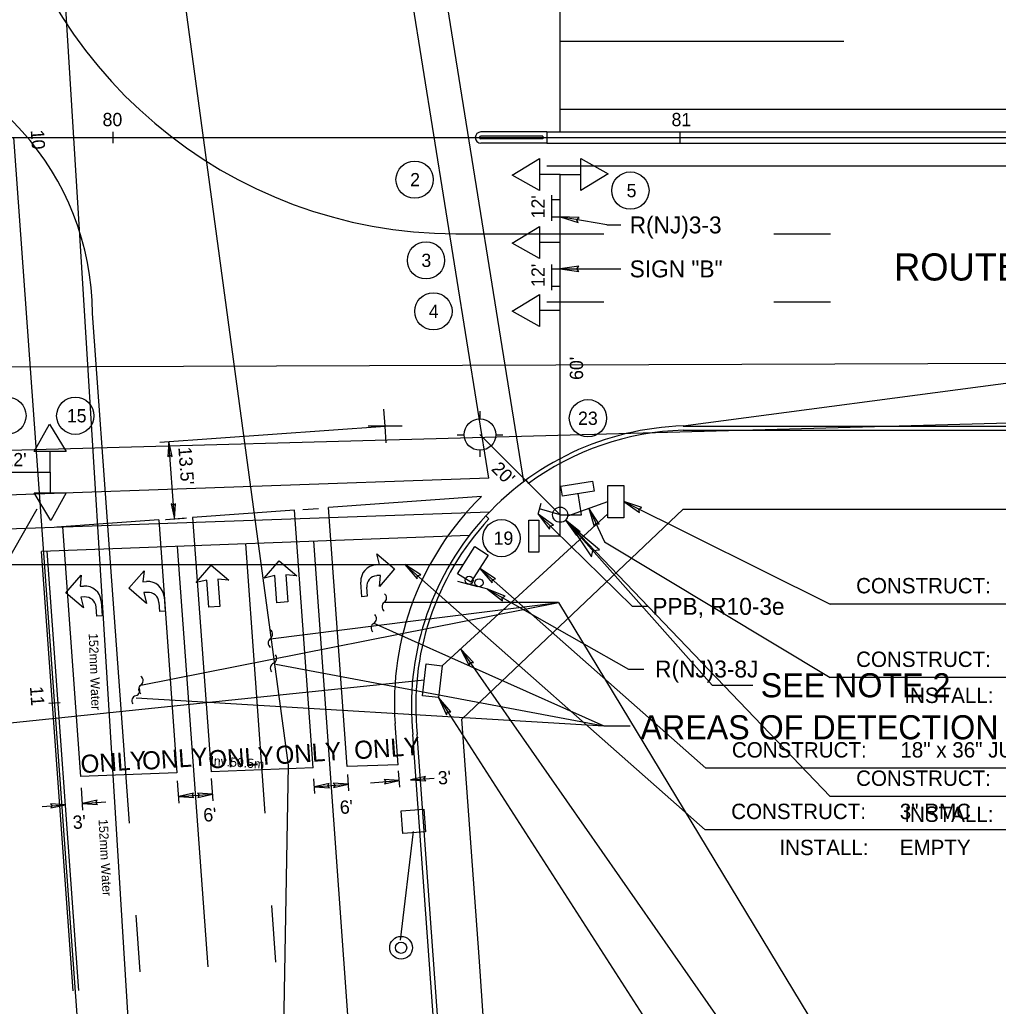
# Model space of a CAD drawing. Extents: x 488740 to 507913, y 466518 to 497949.
# Drawn here: x 503498.7 to 503671.5, y 495917 to 496091.2 of the extents above; entities that cross this region are included whole.
import ezdxf

# ---------------------------------------------------------------- set-up
doc = ezdxf.new("R2010")
doc.units = 0
for name, color, linetype in [('1', 7, 'Continuous'), ('10', 7, 'Continuous'), ('12', 7, 'Continuous'), ('23', 7, 'Continuous'), ('32', 7, 'Continuous'), ('34', 7, 'Continuous'), ('36', 7, 'Continuous'), ('42', 7, 'Continuous'), ('6', 7, 'Continuous'), ('8', 7, 'Continuous')]:
    doc.layers.add(name, color=color, linetype=linetype)

msp = doc.modelspace()

# ---------------------------------------------------------------- linework, layer by layer
at = {"layer": '1'}
for p, q in [((503515.17, 496071.42), (503515.17, 496069.41)), ((503591.84, 496071.42), (503580.19, 496071.42)), ((503591.09, 496070.67), (503580.19, 496070.66)), ((503591.09, 496070.67), (503591.09, 496070.16)), ((503591.84, 496071.42), (503591.84, 496069.41)), ((503591.84, 496071.42), (503748.62, 496071.42)), ((503615.33, 496071.42), (503615.33, 496069.41)), ((503325.93, 496070.42), (503748.62, 496070.42)), ((503515.23, 495827.41), (503497.67, 496070.42)), ((503591.09, 496070.16), (503580.19, 496070.16)), ((503591.84, 496069.41), (503580.19, 496069.41)), ((503591.84, 496069.41), (503748.62, 496069.41)), ((503615.9, 496019.46), (503748.62, 496019.46)), ((503615.9, 496018.71), (503748.62, 496018.71)), ((503588.13, 496009.91), (503588.56, 496009.3)), ((503576.81, 495967.65), (503615.9, 496004.77)), ((503615.9, 496004.77), (503748.62, 496004.77)), ((503581.03, 496003.57), (503581.57, 496003.05)), ((503505.88, 495970.59), (503503.88, 495970.44)), ((503579.91, 495924.86), (503576.81, 495967.65)), ((503574.61, 495875.73), (503568.16, 495964.96)), ((503575.36, 495875.79), (503568.91, 495965.02))]:
    msp.add_line(p, q, dxfattribs=at)
msp.add_lwpolyline([(503566.12, 495951.5), (503570.11, 495951.79), (503570.4, 495947.8), (503566.41, 495947.51)], close=True, dxfattribs=at)
for radius in [2, 0.999]:
    msp.add_circle((503566.07, 495927.31), radius, dxfattribs=at)
for centre, radius, start, end in [((503580.19, 496070.41), 1, 90.0115, 270.0057), ((503580.19, 496070.41), 0.25, 90.0115, 270.0057), ((503617.39, 495970.01), 49.48, 91.7169, 185.8503), ((503617.39, 495970.01), 48.73, 91.7169, 126.2672), ((503617.39, 495970.01), 48.73, 137.2988, 185.8503), ((496341.87, 495401.78), 7256.91, 3.252403, 4.133489)]:
    msp.add_arc(centre, radius, start, end, dxfattribs=at)
at = {"layer": '10'}
for p, q in [((503605.42, 496006.11), (503641.84, 495988.01)), ((503595.1, 496002.82), (503641.84, 495954.01)), ((503520.11, 495973.71), (503593.88, 495988.3)), ((503542.99, 495981.89), (503593.88, 495988.3)), ((503593.88, 495988.3), (503563.1, 495988.31)), ((503593.88, 495988.3), (503641.84, 495909.01)), ((503770.46, 495988.01), (503641.84, 495988.01)), ((503576.6, 495980.13), (503641.84, 495886.46)), ((503770.46, 495975.01), (503641.84, 495975.01)), ((503572.7, 495971.48), (503641.84, 495863.9)), ((503770.46, 495954.01), (503641.84, 495954.01))]:
    msp.add_line(p, q, dxfattribs=at)
for points in [[(503605.42, 496006.11), (503608.17, 496004.21), (503608.07, 496004.79), (503608.59, 496005.06)], [(503599.21, 496004.92), (503600.19, 496001.72), (503600.47, 496002.25), (503601.04, 496002.13)], [(503595.1, 496002.82), (503597.05, 496000.1), (503597.14, 496000.69), (503597.73, 496000.76)], [(503576.6, 495980.13), (503578.1, 495977.14), (503578.29, 495977.7), (503578.88, 495977.68)], [(503572.7, 495971.48), (503574.09, 495968.44), (503574.3, 495969), (503574.89, 495968.95)]]:
    msp.add_lwpolyline(points, close=True, dxfattribs=at)
msp.add_lwpolyline([(503599.21, 496004.92), (503602, 495999.01), (503641.84, 495975.01)], dxfattribs=at)
for centre, radius, start, end in [((503562.58, 495989.08), 0.936, 303.8592, 54.125), ((503563.67, 495987.54), 0.959, 126.4448, 232.814), ((503543.56, 495981.12), 0.959, 126.4448, 232.814), ((503542.46, 495982.67), 0.936, 303.8592, 54.125), ((503519.59, 495974.48), 0.936, 303.8592, 54.125), ((503520.68, 495972.93), 0.959, 126.4448, 232.814)]:
    msp.add_arc(centre, radius, start, end, dxfattribs=at)
at = {"layer": '12'}
for p, q in [((503621.04, 495973.66), (503596.01, 496001.91)), ((503619.78, 495948.14), (503566.77, 495995)), ((503619.89, 495959.01), (503579.98, 495994.28)), ((503621.04, 495973.66), (503628.22, 495973.66)), ((503748.52, 495959.01), (503619.89, 495959.01)), ((503748.4, 495948.14), (503619.78, 495948.14))]:
    msp.add_line(p, q, dxfattribs=at)
for points in [[(503596.01, 496001.91), (503599.69, 495996.33), (503599.93, 495997.49), (503601.11, 495997.59)], [(503566.77, 495995), (503568.93, 495992.45), (503568.98, 495993.04), (503569.56, 495993.16)], [(503579.98, 495994.28), (503582.15, 495991.74), (503582.2, 495992.33), (503582.77, 495992.45)]]:
    msp.add_lwpolyline(points, close=True, dxfattribs=at)
at = {"layer": '23'}
for p, q in [((503524.39, 495809.94), (503494.31, 496296.44)), ((503524.31, 496120.55), (503546.14, 495959.54)), ((503346.41, 496029.35), (503748.62, 496030.81)), ((503469.08, 496014.43), (503748.62, 496022.1)), ((503546.14, 495959.54), (503543.42, 495811.02)), ((503565.97, 495928.67), (503568.29, 495947.86))]:
    msp.add_line(p, q, dxfattribs=at)
at = {"layer": '32'}
for p, q in [((503594.18, 496063.88), (503590.51, 496063.88)), ((503594.18, 496003.79), (503594.18, 496063.88)), ((503594.18, 496063.88), (503597.84, 496063.88)), ((503592.66, 496060.21), (503592.66, 496055.71)), ((503592.66, 496059.46), (503594.17, 496059.46)), ((503592.66, 496056.43), (503594.17, 496056.43)), ((503602.39, 496054.97), (503594.17, 496056.43)), ((503602.39, 496054.97), (503604.87, 496054.97)), ((503594.18, 496051.86), (503590.51, 496051.86)), ((503592.66, 496047.97), (503592.66, 496043.46)), ((503592.66, 496047.21), (503594.18, 496047.21)), ((503594.18, 496047.21), (503604.87, 496047.21)), ((503592.66, 496044.18), (503594.18, 496044.18)), ((503594.18, 496039.84), (503590.51, 496039.84)), ((503563.24, 496019.46), (503563.03, 496022.46)), ((503523.47, 496016.59), (503563.24, 496019.46)), ((503563.24, 496019.46), (503560.24, 496019.46)), ((503566.25, 496019.46), (503563.24, 496019.46)), ((503563.46, 496016.47), (503563.24, 496019.46)), ((503526.07, 496003.08), (503525.08, 496016.71)), ((503526.07, 496003.08), (503525.08, 496016.71)), ((503504.11, 496011.3), (503504.11, 496014.96)), ((503464.05, 496011.3), (503504.11, 496011.3)), ((503504.11, 496011.3), (503504.11, 496007.64)), ((503594.18, 496003.79), (503594.18, 496011)), ((503580.29, 496006.99), (503553.24, 496005.04)), ((503597.95, 496003.79), (503597.36, 496007.52)), ((503495.29, 495993.35), (503501.81, 496004.81)), ((503547.25, 496004.61), (503529.26, 496003.3)), ((503550.54, 495959.06), (503547.25, 496004.61)), ((503548.71, 496004.71), (503551.49, 496004.91)), ((503556.55, 495959.29), (503553.24, 496005.04)), ((503590.28, 496003.91), (503590.83, 496005.84)), ((503594.18, 496003.79), (503590.54, 496004.82)), ((503523.27, 496002.87), (503505.29, 496001.57)), ((503523.27, 496002.87), (503526.5, 495958.17)), ((503524.46, 496002.96), (503528.21, 496003.23)), ((503524.46, 496002.96), (503527.75, 496003.2)), ((503524.54, 496002.96), (503527.64, 496003.19)), ((503529.26, 496003.3), (503532.51, 495958.39)), ((503594.18, 496000.01), (503594.18, 496003.79)), ((503594.18, 496003.79), (503597.95, 496003.79)), ((503506.28, 496001.64), (503509.47, 495957.53)), ((503594.18, 496000.01), (503590.4, 496000.01)), ((503565.54, 495959.63), (503565.01, 495966.93)), ((503550.54, 495959.06), (503532.51, 495958.39)), ((503565.54, 495959.63), (503556.55, 495959.29)), ((503526.5, 495958.17), (503509.47, 495957.53)), ((503556.86, 495955), (503556.65, 495957.9)), ((503565.83, 495955.65), (503565.62, 495958.55)), ((503526.89, 495952.83), (503526.6, 495956.78)), ((503532.88, 495953.26), (503532.6, 495957.21)), ((503550.86, 495954.56), (503550.68, 495957.11)), ((503550.78, 495955.74), (503556.77, 495956.17)), ((503560.69, 495956.46), (503565.74, 495956.82)), ((503567.76, 495956.97), (503571.9, 495957.27)), ((503509.9, 495951.6), (503509.61, 495955.55)), ((503526.8, 495954.01), (503532.8, 495954.44)), ((503502.69, 495952.27), (503506.82, 495952.57)), ((503509.81, 495952.78), (503513.95, 495953.08))]:
    msp.add_line(p, q, dxfattribs=at)
for points in [[(503590.51, 496061.05), (503585.67, 496063.77), (503590.51, 496066.72)], [(503597.84, 496066.72), (503602.68, 496064), (503597.84, 496061.05)], [(503594.17, 496056.43), (503597.35, 496055.39), (503597.08, 496055.91), (503597.51, 496056.32)], [(503590.51, 496049.03), (503585.67, 496051.75), (503590.51, 496054.7)], [(503594.18, 496047.21), (503597.48, 496046.74), (503597.13, 496047.21), (503597.48, 496047.69)], [(503590.51, 496037.01), (503585.67, 496039.73), (503590.51, 496042.68)], [(503501.28, 496014.96), (503503.99, 496019.8), (503506.95, 496014.96)], [(503525.08, 496016.71), (503524.9, 496014.04), (503525.25, 496014.35), (503525.65, 496014.09)], [(503525.08, 496016.71), (503524.9, 496014.04), (503525.25, 496014.35), (503525.65, 496014.09)], [(503594.56, 496007.07), (503594.28, 496008.82), (503599.87, 496009.72), (503600.15, 496007.97)], [(503506.95, 496007.64), (503504.23, 496002.79), (503501.28, 496007.64)], [(503526.07, 496003.08), (503526.25, 496005.74), (503525.9, 496005.43), (503525.5, 496005.69)], [(503526.07, 496003.08), (503526.25, 496005.74), (503525.9, 496005.43), (503525.5, 496005.69)], [(503590.4, 495997.17), (503588.62, 495997.17), (503588.62, 496002.84), (503590.4, 496002.84)], [(503567.76, 495956.97), (503570.43, 495956.78), (503570.12, 495957.14), (503570.37, 495957.54)], [(503550.78, 495955.74), (503553.44, 495955.55), (503553.13, 495955.91), (503553.39, 495956.31)], [(503556.77, 495956.17), (503554.11, 495956.36), (503554.42, 495956), (503554.16, 495955.61)], [(503565.74, 495956.82), (503563.08, 495957.01), (503563.39, 495956.65), (503563.13, 495956.25)], [(503526.8, 495954.01), (503529.47, 495953.82), (503529.16, 495954.18), (503529.41, 495954.58)], [(503532.8, 495954.44), (503530.13, 495954.63), (503530.44, 495954.27), (503530.18, 495953.87)], [(503506.82, 495952.57), (503504.16, 495952.75), (503504.47, 495952.4), (503504.21, 495952)], [(503509.81, 495952.78), (503512.48, 495952.6), (503512.17, 495952.95), (503512.43, 495953.35)]]:
    msp.add_lwpolyline(points, close=True, dxfattribs=at)
for centre, radius in [((503568.47, 496062.98), 3.29), ((503606.58, 496061.05), 3.29), ((503570.48, 496048.72), 3.29), ((503571.79, 496039.72), 3.29), ((503496.55, 496021.28), 3.29), ((503508.54, 496021.27), 3.29), ((503599.08, 496020.84), 3.29), ((503594.18, 496003.79), 1.34), ((503583.81, 495999.65), 3.29)]:
    msp.add_circle(centre, radius, dxfattribs=at)
msp.add_arc((503615.9, 495970.47), 51.01, 134.2818, 183.9813, dxfattribs=at)
at = {"layer": '34'}
for p, q in [((503561.27, 495984.62), (503601.89, 495966.48)), ((503543.98, 495977.41), (503601.89, 495966.48)), ((503519.28, 495971.45), (503601.89, 495966.48)), ((503601.89, 495966.48), (503606.52, 495966.48))]:
    msp.add_line(p, q, dxfattribs=at)
for centre, radius, start, end in [((503560.78, 495985.44), 0.959, 300.8308, 47.2), ((503561.71, 495983.79), 0.936, 118.2452, 228.511), ((503543.16, 495978.43), 0.959, 294.6692, 41.0384), ((503543.91, 495976.69), 0.936, 112.0836, 222.3494), ((503518.96, 495972.75), 0.959, 286.6804, 33.0496), ((503519.46, 495970.92), 0.936, 104.0948, 214.3606)]:
    msp.add_arc(centre, radius, start, end, dxfattribs=at)
at = {"layer": '36'}
for p, q in [((503581.59, 496010.27), (503561.88, 496133.12)), ((503587.77, 496009.65), (503567.97, 496133.08)), ((503594.18, 496071.42), (503594.17, 496133.12)), ((503594.17, 496087.42), (503644.25, 496087.42)), ((503594.18, 496075.4), (503748.62, 496075.4)), ((503591.84, 496065.43), (503748.62, 496065.43)), ((503575.74, 496053.41), (503591.84, 496053.41)), ((503591.84, 496053.41), (503601.86, 496053.41)), ((503631.91, 496053.41), (503641.92, 496053.41)), ((503591.84, 496041.39), (503601.86, 496041.39)), ((503631.91, 496041.39), (503641.92, 496041.39)), ((503514.6, 495997.75), (503511.6, 496039.35)), ((503691.02, 496029.37), (503615.91, 496019.46)), ((503581.59, 496010.27), (503472.76, 496006.44)), ((503581.68, 496004.26), (503473.37, 496000.44)), ((503578.13, 496000.12), (503502.58, 495997.3)), ((503518.1, 495949.33), (503514.6, 495997.75)), ((503531.99, 495923.92), (503526.62, 495998.2)), ((503542.08, 495951.06), (503538.64, 495998.65)), ((503559.65, 495874.65), (503550.66, 495999.1)), ((503508.19, 495919.68), (503502.58, 495997.3)), ((503509.19, 495919.75), (503503.59, 495997.34)), ((503541.89, 495992.58), (503544.56, 495995.66)), ((503544.56, 495995.66), (503547.64, 495992.99)), ((503562.28, 495995), (503561.82, 495996.89)), ((503561.82, 495996.89), (503564.9, 495994.22)), ((503529.89, 495991.79), (503532.56, 495994.88)), ((503532.56, 495994.88), (503535.65, 495992.21)), ((503561.64, 495994.95), (503562.28, 495995)), ((503564.9, 495994.22), (503562.24, 495991.14)), ((503506.9, 495990), (503509.57, 495993.09)), ((503509.57, 495993.09), (503509.39, 495991.15)), ((503518.01, 495990.8), (503520.68, 495993.89)), ((503520.68, 495993.89), (503520.5, 495991.95)), ((503531.79, 495992.25), (503529.89, 495991.79)), ((503532.13, 495987.45), (503531.79, 495992.25)), ((503535.65, 495992.21), (503533.71, 495992.39)), ((503533.71, 495992.39), (503534.05, 495987.59)), ((503543.78, 495993.04), (503541.89, 495992.58)), ((503544.13, 495988.24), (503543.78, 495993.04)), ((503547.64, 495992.99), (503545.7, 495993.18)), ((503545.7, 495993.18), (503546.05, 495988.38)), ((503562.42, 495993.08), (503561.78, 495993.03)), ((503562.24, 495991.14), (503562.42, 495993.08)), ((503509.39, 495991.15), (503510.02, 495991.19)), ((503521.09, 495988.13), (503518.01, 495990.8)), ((503520.5, 495991.95), (503521.14, 495991.99)), ((503559.15, 495989.31), (503558.97, 495991.87)), ((503560, 495990.98), (503560.11, 495989.38)), ((503509.98, 495987.33), (503506.9, 495990)), ((503510.16, 495989.27), (503509.52, 495989.23)), ((503509.52, 495989.23), (503509.98, 495987.33)), ((503521.28, 495990.08), (503520.64, 495990.03)), ((503520.64, 495990.03), (503521.09, 495988.13)), ((503524.22, 495989.32), (503524.41, 495986.77)), ((503560.11, 495989.38), (503559.15, 495989.31)), ((503512.34, 495985.9), (503512.22, 495987.49)), ((503513.11, 495988.52), (503513.29, 495985.96)), ((503523.45, 495986.7), (503523.33, 495988.3)), ((503534.05, 495987.59), (503532.13, 495987.45)), ((503546.05, 495988.38), (503544.13, 495988.24)), ((503513.29, 495985.96), (503512.34, 495985.9)), ((503524.41, 495986.77), (503523.45, 495986.7)), ((503543.98, 495924.78), (503543.25, 495934.77)), ((503520, 495923.05), (503519.28, 495933.04))]:
    msp.add_line(p, q, dxfattribs=at)
for centre, radius, start, end in [((503575.88, 496135.92), 82.51, 189.6092, 269.9061), ((503463.07, 496039.06), 48.52, 0.3384, 83.5869), ((503561.85, 495992.07), 2.88, 94.1344, 184.1344), ((503561.92, 495991.11), 1.92, 94.1344, 184.1344), ((503510.23, 495988.31), 2.88, 4.1344, 94.1344), ((503521.34, 495989.12), 2.88, 4.1344, 94.1344), ((503510.3, 495987.35), 1.92, 4.1344, 94.1344), ((503521.41, 495988.16), 1.92, 4.1344, 94.1344)]:
    msp.add_arc(centre, radius, start, end, dxfattribs=at)
at = {"layer": '42'}
for p, q in [((503590.28, 496003.91), (503606.9, 495987.62)), ((503579.64, 495991.08), (503576.1, 495992)), ((503581.38, 495990.64), (503577.84, 495991.56)), ((503581.36, 495990.65), (503606.24, 495976.53)), ((503606.9, 495987.62), (503609.6, 495987.62)), ((503606.24, 495976.53), (503608.95, 495976.53))]:
    msp.add_line(p, q, dxfattribs=at)
for points in [[(503590.28, 496003.91), (503592.31, 496001.25), (503592.39, 496001.84), (503592.97, 496001.93)], [(503581.36, 495990.65), (503584, 495988.6), (503583.93, 495989.19), (503584.47, 495989.43)]]:
    msp.add_lwpolyline(points, close=True, dxfattribs=at)
for centre in [(503578.11, 495992.21), (503579.84, 495991.77)]:
    msp.add_circle(centre, 0.721, dxfattribs=at)
at = {"layer": '6'}
for p, q in [((503595.5, 496003.61), (503602.57, 496006.11)), ((503573.32, 495977.12), (503602.57, 496003.97)), ((503460.23, 495995), (503577.07, 495995)), ((503473.57, 495964.59), (503570.19, 495974.61))]:
    msp.add_line(p, q, dxfattribs=at)
for points in [[(503602.57, 496003.27), (503602.57, 496008.94), (503605.41, 496008.94), (503605.41, 496003.27)], [(503576.03, 495993.37), (503579.09, 495998.15), (503581.48, 495996.62), (503578.42, 495991.85)], [(503569.88, 495971.79), (503570.5, 495977.43), (503573.32, 495977.12), (503572.7, 495971.48)]]:
    msp.add_lwpolyline(points, close=True, dxfattribs=at)
at = {"layer": '8'}
for p, q in [((503579.99, 496022.06), (503579.99, 496020.73)), ((503576, 496017.93), (503577.23, 496017.93)), ((503580.01, 496017.95), (503594.18, 496003.79)), ((503582.79, 496017.93), (503584.02, 496017.93)), ((503579.99, 496015.17), (503579.99, 496014.02))]:
    msp.add_line(p, q, dxfattribs=at)
msp.add_circle((503580.01, 496017.95), 2.78, dxfattribs=at)

# ---------------------------------------------------------------- texts
at = {"layer": '1'}
for s, rotation, p in [('80', 0, (503513.36, 496072.42)), ('81', 0, (503613.84, 496072.42)), ('10', 274.1335, (503500.66, 496071.71)), ('11', 274.1335, (503500.52, 495973.42))]:
    msp.add_text(s, height=2.344, rotation=rotation, dxfattribs=at).set_placement(p)
msp.add_text('ROUTE  00', height=4.796, dxfattribs=at).set_placement((503653.14, 496045.16))
at = {"layer": '10'}
for s, p in [('CONSTRUCT:', (503646.44, 495989.9)), ('CONSTRUCT:', (503646.44, 495976.9)), ('INSTALL:', (503654.95, 495970.53)), ('CONSTRUCT:', (503646.44, 495955.9)), ('INSTALL:', (503654.95, 495949.53))]:
    msp.add_text(s, height=2.716, dxfattribs=at).set_placement(p)
at = {"layer": '12'}
for s, height, p in [('SEE NOTE 2', 4.255, (503629.59, 495971.54)), ('CONSTRUCT:', 2.716, (503624.5, 495960.9)), ('18" x 36" JUNCTION BOX             ', 2.7163, (503654.26, 495960.9)), ('CONSTRUCT:', 2.716, (503624.38, 495950.03)), ('3" RMC                             ', 2.7163, (503654.15, 495950.03)), ('INSTALL:', 2.716, (503632.89, 495943.66)), ('EMPTY                                          ', 2.7163, (503654.15, 495943.66))]:
    msp.add_text(s, height=height, dxfattribs=at).set_placement(p)
at = {"layer": '23'}
for s, height, rotation, p in [('152mm Water', 1.6204, 272.1445, (503510.91, 495982.84)), ('Inv.50.5m', 1.62, 356.0653, (503532.36, 495959.56)), ('152mm Water', 1.6205, 273.0647, (503512.65, 495949.98))]:
    msp.add_text(s, height=height, rotation=rotation, dxfattribs=at).set_placement(p)
at = {"layer": '32'}
for s, height, p in [('2', 2.34, (503567.68, 496061.81)), ('5', 2.34, (503605.91, 496059.88)), ('R(NJ)3-3', 2.993, (503606.45, 496053.48)), ('3', 2.34, (503569.66, 496047.55)), ('SIGN "B"', 2.993, (503606.45, 496045.72)), ('4', 2.34, (503570.97, 496038.55)), ('15', 2.344, (503507.05, 496020.1)), ('23', 2.344, (503597.33, 496019.66)), ("12'", 2.344, (503495.85, 496012.35)), ('19', 2.344, (503582.41, 495998.48))]:
    msp.add_text(s, height=height, dxfattribs=at).set_placement(p)
for s, rotation, p in [("12'", 90, (503591.43, 496056.13)), ("12'", 90, (503591.43, 496044.03)), ("60'", 90, (503598.22, 496027.6)), ("13.5'", 274.1335, (503526.73, 496015.69)), ("13.5'", 274.1335, (503526.73, 496015.69)), ("3'", 4.134, (503572.67, 495956.11)), ("6'", 4.134, (503555.34, 495950.91)), ("3'", 4.134, (503508.17, 495948.26)), ("6'", 4.134, (503531.23, 495949.55))]:
    msp.add_text(s, height=2.344, rotation=rotation, dxfattribs=at).set_placement(p)
at = {"layer": '34'}
msp.add_text('AREAS OF DETECTION', height=4.2548, dxfattribs=at).set_placement((503608.36, 495964.12))
at = {"layer": '36'}
for p in [(503557.91, 495960.58), (503520.45, 495958.71), (503532.14, 495958.93), (503544.01, 495959.7), (503509.59, 495958.12)]:
    msp.add_text('ONLY', height=3.193, rotation=3.8987, dxfattribs=at).set_placement(p)
at = {"layer": '42'}
for s, height, p in [('PPB, R10-3e', 2.9928, (503610.45, 495986.11)), ('R(NJ)3-8J', 2.993, (503610.94, 495975.04))]:
    msp.add_text(s, height=height, dxfattribs=at).set_placement(p)
at = {"layer": '8'}
msp.add_text("20'", height=2.344, rotation=314.9996, dxfattribs=at).set_placement((503581.88, 496011.74))

doc.saveas('drawing.dxf')
